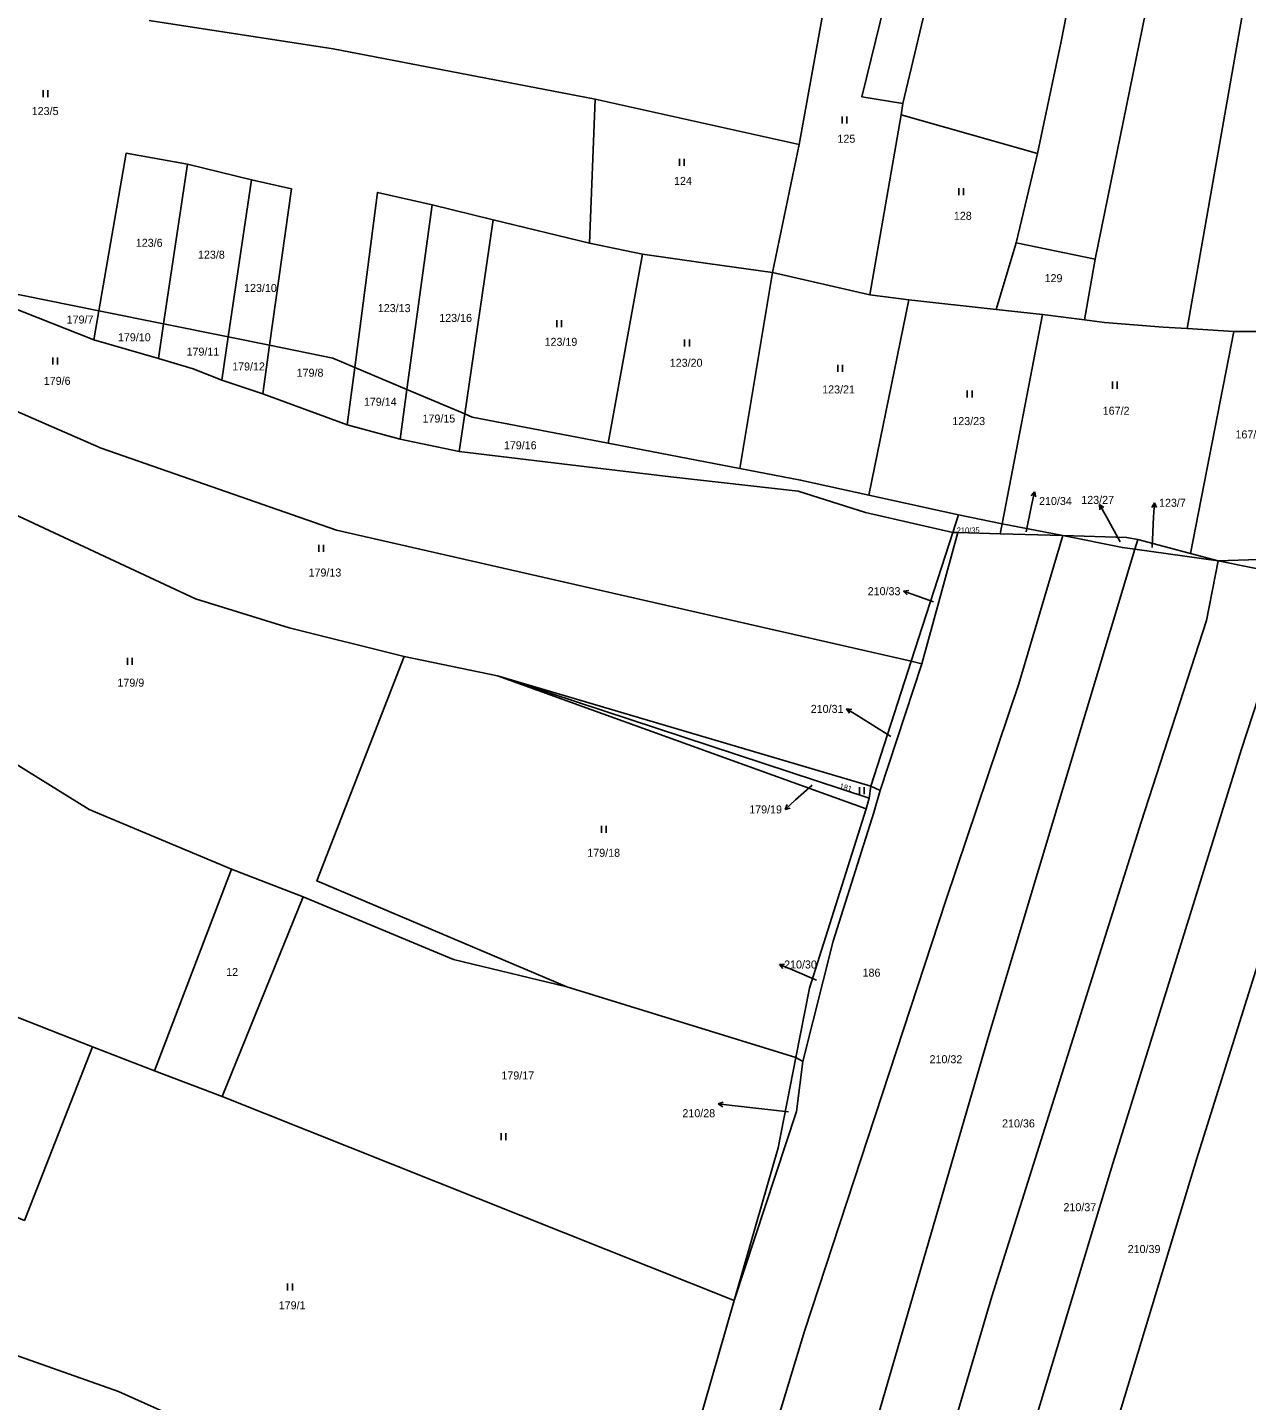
# Model space of a CAD drawing. Extents: x -744566 to -741843, y -1128407 to -1126744.
# Drawn here: x -742757.6 to -742498.8, y -1127637.5 to -1127345.9 of the extents above; entities that cross this region are included whole.
import ezdxf

# ---------------------------------------------------------------- set-up
doc = ezdxf.new("R2010")
doc.units = 0
for name, color, linetype in [('Hranice parcel', 7, 'Continuous'), ('Parcelní čísla', 7, 'Continuous'), ('Pop  PČ popisy', 7, 'Continuous'), ('Značky kultur', 7, 'Continuous')]:
    doc.layers.add(name, color=color, linetype=linetype)

msp = doc.modelspace()

# ---------------------------------------------------------------- linework, layer by layer
at = {"layer": 'Hranice parcel'}
for p, q in [((-742638.23, -1127391.73), (-742637.04, -1127361.12)), ((-742637.04, -1127361.12), (-742593.77, -1127370.76)), ((-742571.73, -1127362.05), (-742572.09, -1127364.45)), ((-742578.78, -1127402.69), (-742572.09, -1127364.45)), ((-742572.09, -1127364.45), (-742543.19, -1127372.64)), ((-742599.43, -1127397.9), (-742593.77, -1127370.76)), ((-742543.19, -1127372.64), (-742547.67, -1127391.65)), ((-742728.68, -1127408.84), (-742723.61, -1127374.95)), ((-742723.61, -1127374.95), (-742709.98, -1127378.27)), ((-742714.95, -1127411.61), (-742709.98, -1127378.27)), ((-742677.01, -1127422.76), (-742671.68, -1127383.55)), ((-742671.68, -1127383.55), (-742658.73, -1127386.75)), ((-742664.74, -1127427.96), (-742658.73, -1127386.75)), ((-742658.73, -1127386.75), (-742638.23, -1127391.73)), ((-742551.9, -1127405.77), (-742547.67, -1127391.65)), ((-742547.67, -1127391.65), (-742530.91, -1127395.09)), ((-742626.99, -1127394), (-742638.23, -1127391.73)), ((-742634.26, -1127434.17), (-742626.99, -1127394)), ((-742530.91, -1127395.09), (-742533.18, -1127408)), ((-742743.5, -1127412.2), (-742776.69, -1127399.15)), ((-742776.69, -1127399.15), (-742742.44, -1127406.06)), ((-742606.32, -1127439.53), (-742599.43, -1127397.9)), ((-742578.78, -1127402.69), (-742599.43, -1127397.9)), ((-742570.47, -1127403.73), (-742578.78, -1127402.69)), ((-742743.5, -1127412.2), (-742742.44, -1127406.06)), ((-742742.44, -1127406.06), (-742728.68, -1127408.84)), ((-742578.95, -1127445.21), (-742570.47, -1127403.73)), ((-742551.9, -1127405.77), (-742570.47, -1127403.73)), ((-742542.09, -1127406.85), (-742551.9, -1127405.77)), ((-742729.77, -1127416.16), (-742728.68, -1127408.84)), ((-742728.68, -1127408.84), (-742714.95, -1127411.61)), ((-742550.64, -1127451.27), (-742542.09, -1127406.85)), ((-742542.09, -1127406.85), (-742533.18, -1127408)), ((-742716.31, -1127420.78), (-742714.95, -1127411.61)), ((-742714.95, -1127411.61), (-742706.16, -1127413.39)), ((-742511.41, -1127409.84), (-742501.5, -1127410.43)), ((-742501.5, -1127410.43), (-742510.66, -1127457.59)), ((-742501.5, -1127410.43), (-742492.74, -1127410.43)), ((-742729.77, -1127416.16), (-742743.5, -1127412.2)), ((-742706.16, -1127413.39), (-742707.61, -1127423.69)), ((-742707.61, -1127423.69), (-742716.31, -1127420.78)), ((-742689.66, -1127430.29), (-742688.08, -1127418.07)), ((-742688.08, -1127418.07), (-742677.01, -1127422.76)), ((-742689.66, -1127430.29), (-742707.61, -1127423.69)), ((-742678.44, -1127433.32), (-742677.01, -1127422.76)), ((-742677.01, -1127422.76), (-742664.74, -1127427.96)), ((-742665.91, -1127435.97), (-742664.74, -1127427.96)), ((-742678.44, -1127433.32), (-742689.66, -1127430.29)), ((-742665.91, -1127435.97), (-742678.44, -1127433.32)), ((-742634.26, -1127434.17), (-742606.32, -1127439.53)), ((-742578.95, -1127445.21), (-742559.94, -1127449.42)), ((-742561.14, -1127453.13), (-742559.94, -1127449.42)), ((-742559.94, -1127449.42), (-742550.64, -1127451.27)), ((-742550.64, -1127451.27), (-742551.05, -1127453.42)), ((-742550.64, -1127451.27), (-742537.81, -1127453.81)), ((-742569.95, -1127480.48), (-742561.14, -1127453.13)), ((-742560.06, -1127453.16), (-742567.73, -1127481)), ((-742560.06, -1127453.16), (-742561.14, -1127453.13)), ((-742551.05, -1127453.42), (-742560.06, -1127453.16)), ((-742537.81, -1127453.81), (-742551.05, -1127453.42)), ((-742521.86, -1127454.6), (-742522.49, -1127456.7)), ((-742510.66, -1127457.59), (-742521.86, -1127454.6)), ((-742522.49, -1127456.7), (-742504.84, -1127459.15)), ((-742504.84, -1127459.15), (-742510.66, -1127457.59)), ((-742496.21, -1127458.9), (-742504.84, -1127459.15)), ((-742504.84, -1127459.15), (-742487.9, -1127462.57)), ((-742677.58, -1127479.48), (-742657.78, -1127483.59)), ((-742578.5, -1127507.04), (-742569.95, -1127480.48)), ((-742567.73, -1127481), (-742576.53, -1127507.95)), ((-742567.73, -1127481), (-742569.95, -1127480.48)), ((-742657.78, -1127483.59), (-742578.5, -1127507.04)), ((-742579.56, -1127511.82), (-742657.78, -1127483.59)), ((-742578.86, -1127509.59), (-742657.78, -1127483.59)), ((-742578.5, -1127507.04), (-742578.86, -1127509.59)), ((-742576.53, -1127507.95), (-742578.5, -1127507.04)), ((-742579.56, -1127511.82), (-742578.86, -1127509.59)), ((-742730.61, -1127567.49), (-742714.26, -1127524.61)), ((-742699.01, -1127530.54), (-742714.26, -1127524.61)), ((-742716.21, -1127572.93), (-742699.01, -1127530.54)), ((-742818.41, -1127533.18), (-742743.76, -1127562.35)), ((-742594.44, -1127564.65), (-742643.07, -1127549.64)), ((-742730.61, -1127567.49), (-742743.76, -1127562.35)), ((-742592.94, -1127565.49), (-742594.44, -1127564.65)), ((-742716.21, -1127572.93), (-742730.61, -1127567.49)), ((-742607.54, -1127616.24), (-742716.21, -1127572.93)), ((-742626.86, -1127683.46), (-742607.54, -1127616.24))]:
    msp.add_line(p, q, dxfattribs=at)
for points in [[(-742571.73, -1127362.05), (-742565.58, -1127336.15), (-742554.25, -1127280.44), (-742551.83, -1127272.48)], [(-742543.19, -1127372.64), (-742538.11, -1127348.86), (-742526.83, -1127290.76), (-742523.05, -1127277.11)], [(-742530.91, -1127395.09), (-742510.84, -1127296.63), (-742506.04, -1127280.03)], [(-742511.41, -1127409.84), (-742497.94, -1127333.24), (-742489.37, -1127297.91), (-742486.41, -1127283.7)], [(-742582.72, -1127303.04), (-742570.71, -1127320.74), (-742580.44, -1127360.6), (-742571.73, -1127362.05)], [(-742593.77, -1127370.76), (-742586.78, -1127332.31), (-742583.12, -1127305.02)], [(-742731.72, -1127344.4), (-742692.68, -1127350.41), (-742637.04, -1127361.12)], [(-742742.44, -1127406.06), (-742736.64, -1127372.59), (-742723.61, -1127374.95)], [(-742709.98, -1127378.27), (-742701.49, -1127380.16), (-742706.16, -1127413.39)], [(-742688.08, -1127418.07), (-742683.29, -1127380.91), (-742671.68, -1127383.55)], [(-742599.43, -1127397.9), (-742613.15, -1127396.01), (-742626.99, -1127394)], [(-742533.18, -1127408), (-742528.9, -1127408.56), (-742516.49, -1127409.54), (-742511.41, -1127409.84)], [(-742706.16, -1127413.39), (-742692.72, -1127416.1), (-742688.08, -1127418.07)], [(-742782.56, -1127417.54), (-742741.92, -1127435.21), (-742691.94, -1127452.67), (-742569.95, -1127480.48)], [(-742716.31, -1127420.78), (-742722.38, -1127418.4), (-742729.77, -1127416.16)], [(-742664.74, -1127427.96), (-742663.18, -1127428.62), (-742634.26, -1127434.17)], [(-742677.58, -1127479.48), (-742701.98, -1127473.41), (-742721.92, -1127467.25), (-742790.61, -1127435.15)], [(-742561.14, -1127453.13), (-742579.7, -1127448.86), (-742593.95, -1127444.37), (-742621, -1127441.33), (-742635.25, -1127439.62), (-742665.91, -1127435.97)], [(-742606.32, -1127439.53), (-742593.44, -1127442), (-742578.95, -1127445.21)], [(-742617.34, -1127704.25), (-742592.59, -1127622.78), (-742562.59, -1127531.26), (-742547.11, -1127485.27), (-742537.81, -1127453.81)], [(-742521.86, -1127454.6), (-742524.23, -1127454.21), (-742537.81, -1127453.81)], [(-742537.81, -1127453.81), (-742525.12, -1127456.33), (-742522.49, -1127456.7)], [(-742592.33, -1127693.42), (-742553.24, -1127559.15), (-742522.49, -1127456.7)], [(-742574.91, -1127690.26), (-742552.84, -1127615.42), (-742521.15, -1127514.67), (-742507.28, -1127471.86), (-742504.84, -1127459.15)], [(-742557.53, -1127687.75), (-742527.44, -1127588.04), (-742499.87, -1127499.13), (-742487.9, -1127462.57)], [(-742539.98, -1127687.22), (-742509.38, -1127586.29), (-742471.63, -1127465.86)], [(-742643.07, -1127549.64), (-742696.11, -1127527.15), (-742677.58, -1127479.48)], [(-742714.26, -1127524.61), (-742744.44, -1127512), (-742789.88, -1127483.77)], [(-742576.53, -1127507.95), (-742577.87, -1127512.58), (-742586.52, -1127539.9), (-742592.94, -1127565.49)], [(-742594.44, -1127564.65), (-742591.53, -1127549.93), (-742579.56, -1127511.82)], [(-742699.01, -1127530.54), (-742667.09, -1127543.83), (-742643.07, -1127549.64)], [(-742743.76, -1127562.35), (-742758.22, -1127599.23), (-742781.54, -1127589.48), (-742788.73, -1127587.57), (-742823.54, -1127569.02), (-742829.14, -1127567.37)], [(-742607.54, -1127616.24), (-742598.22, -1127583.8), (-742594.44, -1127564.65)], [(-742592.94, -1127565.49), (-742594.28, -1127576.09), (-742607.54, -1127616.24)], [(-742842.01, -1127594.12), (-742781.53, -1127620.27), (-742738.25, -1127635.58), (-742671.97, -1127665.27), (-742626.86, -1127683.46)]]:
    msp.add_lwpolyline(points, dxfattribs=at)
at = {"layer": 'Pop  PČ popisy'}
for p, q in [((-742543.796, -1127444.475), (-742544.494, -1127445.35)), ((-742544.42, -1127447.41), (-742543.796, -1127444.475)), ((-742543.796, -1127444.475), (-742543.514, -1127445.558)), ((-742518.343, -1127446.833), (-742518.895, -1127447.807)), ((-742518.5, -1127449.83), (-742518.343, -1127446.833)), ((-742518.343, -1127446.833), (-742517.895, -1127447.859)), ((-742545.56, -1127453.02), (-742544.42, -1127447.41)), ((-742528.52, -1127449.81), (-742529.975, -1127447.185)), ((-742529.975, -1127447.185), (-742529.051, -1127447.818)), ((-742529.975, -1127447.185), (-742529.927, -1127448.304)), ((-742525.6, -1127455.12), (-742528.52, -1127449.81)), ((-742518.79, -1127456.34), (-742518.5, -1127449.83)), ((-742571.59, -1127465.594), (-742570.478, -1127465.466)), ((-742568.77, -1127466.62), (-742571.59, -1127465.594)), ((-742571.59, -1127465.594), (-742570.82, -1127466.407)), ((-742565.23, -1127467.88), (-742568.77, -1127466.62)), ((-742581.13, -1127492.18), (-742583.675, -1127490.59)), ((-742583.675, -1127490.59), (-742582.56, -1127490.696)), ((-742583.675, -1127490.59), (-742583.091, -1127491.545)), ((-742574.26, -1127496.44), (-742581.13, -1127492.18)), ((-742590.98, -1127506.8), (-742594.5, -1127509.95)), ((-742594.5, -1127509.95), (-742596.73, -1127511.958)), ((-742596.73, -1127511.958), (-742596.321, -1127510.916)), ((-742596.73, -1127511.958), (-742595.651, -1127511.66)), ((-742597.942, -1127544.877), (-742596.825, -1127544.808)), ((-742595.18, -1127546.05), (-742597.942, -1127544.877)), ((-742597.942, -1127544.877), (-742597.216, -1127545.73)), ((-742590.09, -1127548.19), (-742595.18, -1127546.05)), ((-742610.925, -1127574.496), (-742609.876, -1127574.103)), ((-742607.94, -1127574.81), (-742610.925, -1127574.496)), ((-742610.925, -1127574.496), (-742609.981, -1127575.099)), ((-742596.01, -1127576.14), (-742607.94, -1127574.81))]:
    msp.add_line(p, q, dxfattribs=at)
at = {"layer": 'Značky kultur'}
for p, q in [((-742754.241, -1127360.69), (-742754.241, -1127359.19)), ((-742753.24, -1127360.69), (-742753.24, -1127359.19)), ((-742584.601, -1127366.28), (-742584.601, -1127364.78)), ((-742583.6, -1127366.28), (-742583.6, -1127364.78)), ((-742619.181, -1127375.28), (-742619.181, -1127373.78)), ((-742618.18, -1127375.28), (-742618.18, -1127373.78)), ((-742559.871, -1127381.51), (-742559.871, -1127380.01)), ((-742558.87, -1127381.51), (-742558.87, -1127380.01)), ((-742645.221, -1127409.53), (-742645.221, -1127408.03)), ((-742644.22, -1127409.53), (-742644.22, -1127408.03)), ((-742618.061, -1127413.66), (-742618.061, -1127412.16)), ((-742617.06, -1127413.66), (-742617.06, -1127412.16)), ((-742752.151, -1127417.46), (-742752.151, -1127415.96)), ((-742751.15, -1127417.46), (-742751.15, -1127415.96)), ((-742585.521, -1127419.01), (-742585.521, -1127417.51)), ((-742584.52, -1127419.01), (-742584.52, -1127417.51)), ((-742558.051, -1127424.5), (-742558.051, -1127423)), ((-742557.05, -1127424.5), (-742557.05, -1127423)), ((-742527.221, -1127422.61), (-742527.221, -1127421.11)), ((-742526.22, -1127422.61), (-742526.22, -1127421.11)), ((-742695.721, -1127457.24), (-742695.721, -1127455.74)), ((-742694.72, -1127457.24), (-742694.72, -1127455.74)), ((-742736.331, -1127481.24), (-742736.331, -1127479.74)), ((-742735.33, -1127481.24), (-742735.33, -1127479.74)), ((-742580.971, -1127508.69), (-742580.971, -1127507.19)), ((-742579.97, -1127508.69), (-742579.97, -1127507.19)), ((-742635.711, -1127516.94), (-742635.711, -1127515.44)), ((-742634.71, -1127516.94), (-742634.71, -1127515.44)), ((-742657.031, -1127582.2), (-742657.031, -1127580.7)), ((-742656.03, -1127582.2), (-742656.03, -1127580.7)), ((-742702.331, -1127614.12), (-742702.331, -1127612.62)), ((-742701.33, -1127614.12), (-742701.33, -1127612.62))]:
    msp.add_line(p, q, dxfattribs=at)

# ---------------------------------------------------------------- texts
at = {"layer": 'Parcelní čísla'}
for s, height, p in [('123/5', 1.7, (-742756.66, -1127364.49)), ('125', 1.7, (-742585.62, -1127370.37)), ('124', 1.7, (-742620.31, -1127379.33)), ('128', 1.7, (-742560.91, -1127386.74)), ('123/6', 1.7, (-742734.56, -1127392.47)), ('123/8', 1.7, (-742721.36, -1127394.99)), ('123/10', 1.7, (-742711.58, -1127402.06)), ('129', 1.7, (-742541.65, -1127399.98)), ('123/13', 1.7, (-742683.19, -1127406.34)), ('179/7', 1.7, (-742749.24, -1127408.77)), ('123/16', 1.7, (-742670.14, -1127408.42)), ('179/10', 1.7, (-742738.35, -1127412.53)), ('123/19', 1.7, (-742647.79, -1127413.5)), ('179/11', 1.7, (-742723.79, -1127415.59)), ('179/12', 1.7, (-742714.11, -1127418.73)), ('123/20', 1.7, (-742621.22, -1127417.95)), ('179/6', 1.7, (-742754.1, -1127421.79)), ('179/8', 1.7, (-742700.42, -1127420.06)), ('123/21', 1.7, (-742588.86, -1127423.61)), ('179/14', 1.7, (-742686.15, -1127426.23)), ('167/2', 1.7, (-742529.31, -1127428.13)), ('179/15', 1.7, (-742673.7, -1127429.79)), ('123/23', 1.7, (-742561.24, -1127430.33)), ('167/1', 1.7, (-742501.13, -1127433.16)), ('179/16', 1.7, (-742656.43, -1127435.47)), ('210/34', 1.7, (-742542.82, -1127447.303)), ('123/27', 1.7, (-742533.861, -1127447.07)), ('123/7', 1.7, (-742517.36, -1127447.68)), ('210/35', 1.19, (-742560.3, -1127453.265)), ('179/13', 1.7, (-742697.89, -1127462.49)), ('210/33', 1.7, (-742579.201, -1127466.46)), ('179/9', 1.7, (-742738.46, -1127485.88)), ('210/31', 1.7, (-742591.291, -1127491.45)), ('179/19', 1.7, (-742604.351, -1127512.8)), ('179/18', 1.7, (-742638.72, -1127522.01)), ('12', 1.7, (-742715.38, -1127547.33)), ('210/30', 1.7, (-742596.94, -1127545.73)), ('186', 1.7, (-742580.29, -1127547.47)), ('210/32', 1.7, (-742566.07, -1127565.85)), ('179/17', 1.7, (-742656.95, -1127569.3)), ('210/28', 1.7, (-742618.531, -1127577.313)), ('210/36', 1.7, (-742550.67, -1127579.48)), ('210/37', 1.7, (-742537.64, -1127597.27)), ('210/39', 1.7, (-742524.01, -1127606.16)), ('179/1', 1.7, (-742704.22, -1127618.11))]:
    msp.add_text(s, height=height, dxfattribs=at).set_placement(p)
msp.add_text('181', height=1.19, rotation=345, dxfattribs=at).set_placement((-742585.289, -1127507.516))

doc.saveas('drawing.dxf')
